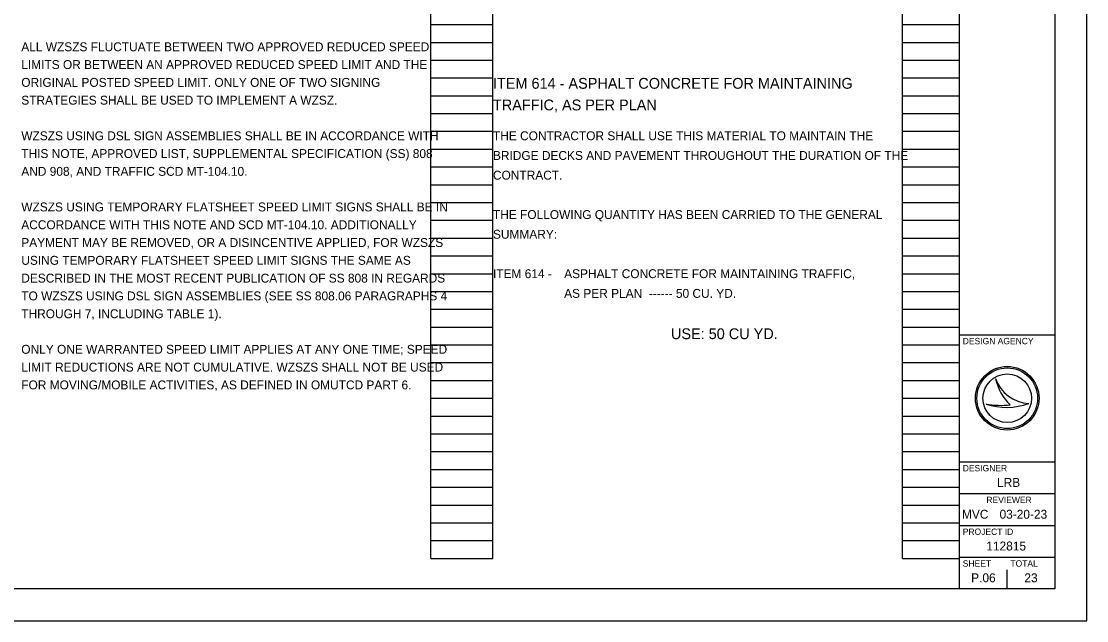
# Model space of a CAD drawing. Extents: x 0 to 34, y 0 to 22.
# Drawn here: x 17.24 to 34, y 0 to 9.43 of the extents above; entities that cross this region are included whole.
import ezdxf

# ---------------------------------------------------------------- set-up
doc = ezdxf.new("R2010")
doc.units = 0
for name, color, linetype in [('SH_Border', 7, 'Continuous'), ('SH_Cut_Line', 7, 'Continuous'), ('SH_Data', 7, 'Continuous'), ('SH_Text', 7, 'Continuous')]:
    doc.layers.add(name, color=color, linetype=linetype)

msp = doc.modelspace()

# ---------------------------------------------------------------- linework, layer by layer
at = {"layer": 'SH_Border'}
for p, q in [((32, 0.5), (32, 21.5)), ((32, 4.5), (33.5, 4.5)), ((32, 2.5), (33.5, 2.5)), ((32, 2), (33.5, 2)), ((32, 1.5), (33.5, 1.5)), ((32, 1), (33.5, 1))]:
    msp.add_line(p, q, dxfattribs=at)
msp.add_lwpolyline([(1.5, 21.5), (33.5, 21.5), (33.5, 0.5), (1.5, 0.5)], close=True, dxfattribs=at)
at = {"layer": 'SH_Cut_Line'}
msp.add_lwpolyline([(0, 0), (34, 0), (34, 22), (0, 22)], close=True, dxfattribs=at)
at = {"layer": 'SH_Data'}
for p, q in [((23.68, 0.98), (23.68, 21.14)), ((24.66, 0.98), (24.66, 21.14)), ((31.1, 0.98), (31.1, 21.14)), ((32, 0.98), (32, 21.14)), ((23.68, 9.38), (24.66, 9.38)), ((31.1, 9.38), (32, 9.38)), ((23.68, 9.1), (24.66, 9.1)), ((31.1, 9.1), (32, 9.1)), ((23.68, 8.82), (24.66, 8.82)), ((31.1, 8.82), (32, 8.82)), ((23.68, 8.54), (24.66, 8.54)), ((31.1, 8.54), (32, 8.54)), ((23.68, 8.26), (24.66, 8.26)), ((31.1, 8.26), (32, 8.26)), ((23.68, 7.98), (24.66, 7.98)), ((31.1, 7.98), (32, 7.98)), ((23.68, 7.7), (24.66, 7.7)), ((31.1, 7.7), (32, 7.7)), ((23.68, 7.42), (24.66, 7.42)), ((31.1, 7.42), (32, 7.42)), ((23.68, 7.14), (24.66, 7.14)), ((31.1, 7.14), (32, 7.14)), ((23.68, 6.86), (24.66, 6.86)), ((31.1, 6.86), (32, 6.86)), ((23.68, 6.58), (24.66, 6.58)), ((31.1, 6.58), (32, 6.58)), ((23.68, 6.3), (24.66, 6.3)), ((31.1, 6.3), (32, 6.3)), ((23.68, 6.02), (24.66, 6.02)), ((31.1, 6.02), (32, 6.02)), ((23.68, 5.74), (24.66, 5.74)), ((31.1, 5.74), (32, 5.74)), ((23.68, 5.46), (24.66, 5.46)), ((31.1, 5.46), (32, 5.46)), ((23.68, 5.18), (24.66, 5.18)), ((31.1, 5.18), (32, 5.18)), ((23.68, 4.9), (24.66, 4.9)), ((31.1, 4.9), (32, 4.9)), ((23.68, 4.62), (24.66, 4.62)), ((31.1, 4.62), (32, 4.62)), ((23.68, 4.34), (24.66, 4.34)), ((31.1, 4.34), (32, 4.34)), ((23.68, 4.06), (24.66, 4.06)), ((31.1, 4.06), (32, 4.06)), ((23.68, 3.78), (24.66, 3.78)), ((31.1, 3.78), (32, 3.78)), ((32.567, 3.81), (32.567, 3.81)), ((23.68, 3.5), (24.66, 3.5)), ((31.1, 3.5), (32, 3.5)), ((32.417, 3.41), (32.417, 3.41)), ((32.75, 3.5), (32.75, 3.5)), ((33.087, 3.419), (33.087, 3.419)), ((23.68, 3.22), (24.66, 3.22)), ((31.1, 3.22), (32, 3.22)), ((23.68, 2.94), (24.66, 2.94)), ((31.1, 2.94), (32, 2.94)), ((23.68, 2.66), (24.66, 2.66)), ((31.1, 2.66), (32, 2.66)), ((23.68, 2.38), (24.66, 2.38)), ((31.1, 2.38), (32, 2.38)), ((23.68, 2.1), (24.66, 2.1)), ((31.1, 2.1), (32, 2.1)), ((23.68, 1.82), (24.66, 1.82)), ((31.1, 1.82), (32, 1.82)), ((23.68, 1.54), (24.66, 1.54)), ((31.1, 1.54), (32, 1.54)), ((23.68, 1.26), (24.66, 1.26)), ((31.1, 1.26), (32, 1.26)), ((23.68, 0.98), (24.66, 0.98)), ((31.1, 0.98), (32, 0.98)), ((32.375, 0.675), (32.375, 0.675)), ((32.75, 0.5), (32.75, 0.8))]:
    msp.add_line(p, q, dxfattribs=at)
for radius in [0.5, 0.477, 0.477, 0.382]:
    msp.add_circle((32.75, 3.5), radius, dxfattribs=at)
for centre, radius, start, end in [((33.116, 3.998), 0.58, 198.9257, 198.9319), ((33.347, 3.97), 0.796, 191.6379, 191.6421), ((33.116, 3.998), 0.58, 198.9319, 267.1657), ((33.347, 3.97), 0.796, 191.6421, 226.0947), ((32.739, 4.37), 1.013, 251.4576, 290.0832), ((32.648, 4.654), 1.266, 259.4964, 259.4995), ((32.739, 4.37), 1.013, 251.4527, 251.4576), ((32.648, 4.654), 1.266, 259.4995, 276.6672)]:
    msp.add_arc(centre, radius, start, end, dxfattribs=at)

# ---------------------------------------------------------------- texts
for s, height, p in [('DESIGN AGENCY', 0.1, (32.05, 4.35)), ('DESIGNER', 0.1, (32.05, 2.35)), ('LRB', 0.14, (32.589, 2.105)), ('REVIEWER', 0.1, (32.422, 1.85)), ('MVC', 0.14, (32.038, 1.605)), ('03-20-23', 0.14, (32.629, 1.605)), ('PROJECT ID', 0.1, (32.05, 1.35)), ('112815', 0.14, (32.421, 1.105)), ('SHEET', 0.1, (32.05, 0.85)), ('TOTAL', 0.1, (32.8, 0.85)), ('P.06', 0.14, (32.183, 0.605)), ('23', 0.14, (33.02, 0.605))]:
    msp.add_text(s, height=height, dxfattribs=at).set_placement(p)
at = {"layer": 'SH_Text'}
for s, height, p in [('ALL WZSZS FLUCTUATE BETWEEN TWO APPROVED REDUCED SPEED ', 0.14, (17.24, 8.96)), ('LIMITS OR BETWEEN AN APPROVED REDUCED SPEED LIMIT AND THE ', 0.14, (17.24, 8.68)), ('ORIGINAL POSTED SPEED LIMIT. ONLY ONE OF TWO SIGNING ', 0.14, (17.24, 8.4)), ('ITEM 614 - ASPHALT CONCRETE FOR MAINTAINING ', 0.17, (24.66, 8.37)), ('STRATEGIES SHALL BE USED TO IMPLEMENT A WZSZ.', 0.14, (17.24, 8.12)), ('TRAFFIC, AS PER PLAN', 0.17, (24.66, 8.03)), ('WZSZS USING DSL SIGN ASSEMBLIES SHALL BE IN ACCORDANCE WITH ', 0.14, (17.24, 7.56)), ('THE CONTRACTOR SHALL USE THIS MATERIAL TO MAINTAIN THE ', 0.14, (24.66, 7.56)), ('THIS NOTE, APPROVED LIST, SUPPLEMENTAL SPECIFICATION (SS) 808 ', 0.14, (17.24, 7.28)), ('BRIDGE DECKS AND PAVEMENT THROUGHOUT THE DURATION OF THE ', 0.14, (24.66, 7.25)), ('AND 908, AND TRAFFIC SCD MT-104.10.', 0.14, (17.24, 7)), ('CONTRACT.', 0.14, (24.66, 6.94)), ('WZSZS USING TEMPORARY FLATSHEET SPEED LIMIT SIGNS SHALL BE IN ', 0.14, (17.24, 6.44)), ('THE FOLLOWING QUANTITY HAS BEEN CARRIED TO THE GENERAL ', 0.14, (24.66, 6.32)), ('ACCORDANCE WITH THIS NOTE AND SCD MT-104.10. ADDITIONALLY ', 0.14, (17.24, 6.16)), ('SUMMARY:', 0.14, (24.66, 6.01)), ('PAYMENT MAY BE REMOVED, OR A DISINCENTIVE APPLIED, FOR WZSZS ', 0.14, (17.24, 5.88)), ('USING TEMPORARY FLATSHEET SPEED LIMIT SIGNS THE SAME AS ', 0.14, (17.24, 5.6)), ('ITEM 614 -', 0.14, (24.66, 5.39)), ('ASPHALT CONCRETE FOR MAINTAINING TRAFFIC, ', 0.14, (25.78, 5.39)), ('DESCRIBED IN THE MOST RECENT PUBLICATION OF SS 808 IN REGARDS ', 0.14, (17.24, 5.32)), ('AS PER PLAN  ------ 50 CU. YD.', 0.14, (25.78, 5.08)), ('TO WZSZS USING DSL SIGN ASSEMBLIES (SEE SS 808.06 PARAGRAPHS 4 ', 0.14, (17.24, 5.04)), ('THROUGH 7, INCLUDING TABLE 1).', 0.14, (17.24, 4.76)), ('USE: 50 CU YD.', 0.17, (27.46, 4.43)), ('ONLY ONE WARRANTED SPEED LIMIT APPLIES AT ANY ONE TIME; SPEED ', 0.14, (17.24, 4.2)), ('LIMIT REDUCTIONS ARE NOT CUMULATIVE. WZSZS SHALL NOT BE USED ', 0.14, (17.24, 3.92)), ('FOR MOVING/MOBILE ACTIVITIES, AS DEFINED IN OMUTCD PART 6.', 0.14, (17.24, 3.64))]:
    msp.add_text(s, height=height, dxfattribs=at).set_placement(p)

doc.saveas('drawing.dxf')
